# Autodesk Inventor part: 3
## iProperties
Created: 2012-03
Part Number: 3
Document SubType Name: Modeling
Designer: Administrator
Density: 7.85 g/cm^3
Material: Steel
Mass: 24.0832 g
Surface Area: 29.4643 cm^2
Volume: 3.06793 cm^3
Translation Standard: STEP AP203
FileName: //expscmdclustefs.cadenas.external/client_exchange/iodir/jobs/output/wkb42693478_no0/STEP/208_9001__24208_90010__2_03.stp
PostProcessor: Build: 236a, Release: 2009 RTM - Date: Fri 02/22/2008
Sent Units: CM
Uncertainty: 0.0
Author: Administrator
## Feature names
1. Base1
